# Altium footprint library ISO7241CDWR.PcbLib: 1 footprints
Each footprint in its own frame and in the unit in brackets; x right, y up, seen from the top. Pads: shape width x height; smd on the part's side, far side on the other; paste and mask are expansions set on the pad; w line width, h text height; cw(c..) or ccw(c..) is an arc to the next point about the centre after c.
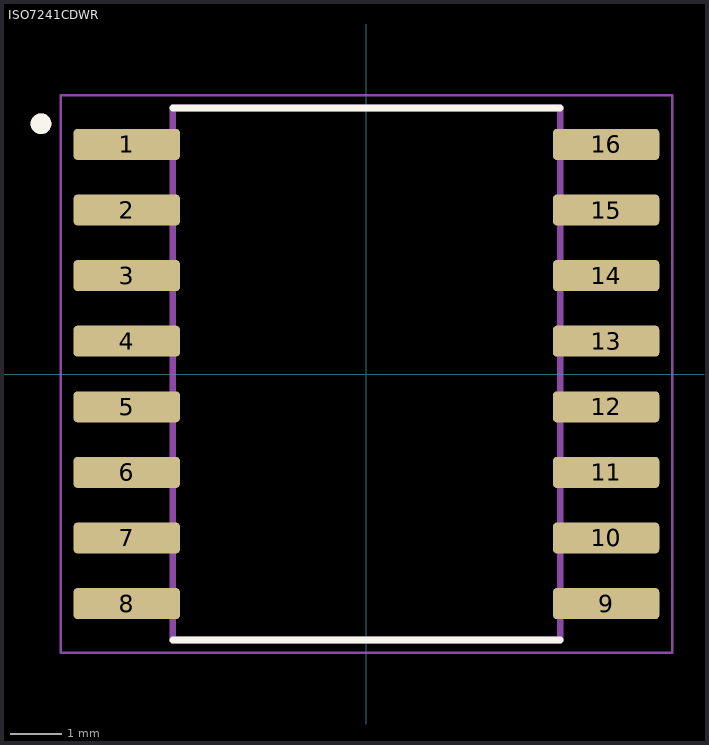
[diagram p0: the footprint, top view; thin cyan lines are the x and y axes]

## ISO7241CDWR [mm]
pads (16):
  rrect25% 2.06x0.6 smd: 1(-4.64,4.445) 2(-4.64,3.175) 3(-4.64,1.905) 4(-4.64,0.635) 5(-4.64,-0.635) 6(-4.64,-1.905) 7(-4.64,-3.175) 8(-4.64,-4.445) 9(4.64,-4.445) 10(4.64,-3.175) 11(4.64,-1.905) 12(4.64,-0.635) 13(4.64,0.635) 14(4.64,1.905) 15(4.64,3.175) 16(4.64,4.445)
Top Overlay:
  circle w0.2: c-6.3,4.845 r0.1
  lines w0.127: -3.75,-5.15 3.75,-5.15 ; -3.75,5.15 3.75,5.15
Mechanical 13:
  circle w0.2: c-6.3,4.845 r0.1
  lines w0.127: -3.75,-5.15 -3.75,5.15 3.75,5.15 3.75,-5.15 -3.75,-5.15
Mechanical 15:
  lines w0.05: -5.92,-5.4 -5.92,5.4 5.92,5.4 5.92,-5.4 -5.92,-5.4
3D body "ISO7241CDWR.STEP": height 2.65, standoff 0, extent -5.08,-5.15 5.22,5.15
